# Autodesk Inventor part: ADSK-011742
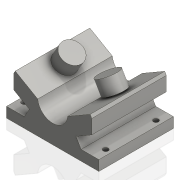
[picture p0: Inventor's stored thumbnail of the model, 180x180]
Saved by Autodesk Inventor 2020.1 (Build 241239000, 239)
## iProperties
Created: 1999-11
Part Number: ADSK-011742
Description: Lee Bearing,1.00,single
Material: Aluminum
Document SubType Name: Modeling
Designer: glanglot
Density: 2.71 g/cm^3
Appearance: Steel
Mass: 350.772 g
Surface Area: 265.608 cm^2
Volume: 129.436 cm^3
Control State: 0
Checked Out: False
Last Check In By: glanglot
Last Check In Date: 6670-11-28
Master: False
Shininess: 0.0
Length Units: 11269
Angle Units: 11279
Time Units: 11290
Mass Units: 11283
Length Display Precision: 3
Angle Display Precision: 2
Compacted: True
Dimensions: 82,6x51,5x66,7 mm
Mass: 0,351 kg
DocNumber: ADSK-011742.ipt
Folder: 01 - Themengebiete\Simplification\01 - Packaging machine\
VDS_Category: 3D Komponenten
Density: 0.0
Volumn: 0.0
Area: 0.0
PropertySet Name: Model Information
Author: glanglot
Revision Number: -
Title: wagoon
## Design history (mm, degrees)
node "Extrusion1" dims "d36" = 66.675, "d37" = 0
node "Hole1" dims "d46" = 4.5, "d47" = 9.525, "d48" = 6.35, "d49" = 60 deg, "d50" = 19.05, "d51" = 118 deg, "d83" = 6
  sketch "Sketch2"
    geometry: L1 (82.55, 66.675)-(82.55, 0) reference; L2 (0, 66.675)-(82.55, 66.675) reference; L3 (77.775, 10.838)-(4.775, 10.838); L4 (4.775, 10.838)-(4.775, 55.837); L5 (4.775, 55.837)-(77.775, 55.838); L6 (77.775, 55.838)-(77.775, 10.838); 6 further points
    constraints: 8 end point, 4 midpoint, 2 coincident, 2 parallel, 1 horizontal, 1 horizontal alignment, 1 perpendicular, 1 vertical alignment
    dimensions: "d81" = 45 distance of L3.end L4.end; "d82" = 73 distance of L3.start L3.end
node "Extrusion2" dims "d55" = 1.5875, "d56" = 0
node "Extrusion3" dims "d58" = 12.7, "d59" = 0
workplane "Work Plane1"
node "Mirror1"
node "Solide1"
node "Corps solides"
node "Corps surfaciques"
sketch "Sketch1"
  geometry: L1 (-41.275, -30.163)-(41.275, -30.163); L2 (41.275, -30.163)-(41.275, -21.019); L3 (41.275, -21.019)-(25.4, -21.019); L4 (-41.275, -30.163)-(-41.275, -21.019); L5 (-41.275, -21.019)-(-25.4, -21.019); L6 (-25.4, -21.019)-(-20.85, -13.138); L7 (-20.85, -13.138)-(-34.925, -5.012); L8 (-34.925, -5.012)-(-34.925, 7.688); L9 (-34.925, 7.688)-(-33.492, 10.171); L10 (-33.492, 10.171)-(-13.419, -1.418); L11 (25.4, -21.019)-(20.85, -13.138); L12 (20.85, -13.138)-(34.925, -5.012); L13 (34.925, -5.012)-(34.925, 7.688); L14 (34.925, 7.688)-(33.492, 10.171); L15 (33.492, 10.171)-(13.419, -1.418); L16 (-36.501, 20.637)-(21.351, 20.637); C1 r 12.7 at (0, 0); A1 r 13.494 centre (0, 0) between (-13.419, -1.418) and (13.419, -1.418); A2 r 13.494 centre (0, 0) between (-13.419, -1.418) and (13.419, -1.418); 1 further point
  constraints: 32 end point, 7 equal length, 5 perpendicular, 5 point on circle, 3 centre point, 3 coincident, 2 parallel, 1 horizontal, 1 point on line, 1 vertical
  dimensions: "d0" = 82.55 distance of L1.start L1.end; "d1" = 9.144 distance of L1.start L4.end; "d2" = 15.875 distance of L4.end L5.end; "d32" = 69.85 distance between parallel lines of L13 L8; "d35" = 120 deg angle of L15 L10; "d64" = 13.49375 radius of A1; "d65" = 30.1625 distance from line of L1 A1.centre; "d66" = 41.275 distance from line of A1.centre L4; "d68" = 40.33342 distance from line of L1 L9.end; "d70" = 17.02451 distance from line of L6.end L1; "d71" = 25.15061 distance from line of L1 L7.end; "d72" = 37.85061 distance from line of L1 L8.end; "d73" = 120 deg angle of L5 L6; "d74" = 90 deg angle of L6 L7; "d75" = 90 deg angle of L10 L9; "d79" = 50.8 distance between parallel lines of L1 L16; "d80" = 25.4 diameter of C1
sketch "Sketch3"
  geometry: L1 (-1.773, 914.4)-(-1.773, 0) reference; L2 (-9.752, 0)-(-9.752, 66.675) reference; C1 r 4.763 at (-11.298, 33.338)
  constraints: 1 centre point, 1 other
  dimensions: "d78" = 9.525 diameter of C1
sketch "Sketch4"
  geometry: C1 r 4.763 at (0, 0) reference; C2 r 9.525 at (0, 0)
  constraints: 1 centre point, 1 coincident
  dimensions: "d57" = 19.05 diameter of C2
other parameters: "d60" = -41.275 (= -0.5 x d0)
